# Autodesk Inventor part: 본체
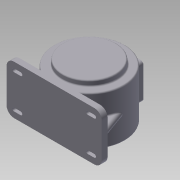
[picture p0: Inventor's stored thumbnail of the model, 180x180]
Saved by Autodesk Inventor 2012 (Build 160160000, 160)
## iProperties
Created: 2015-06
Part Number: 본체
Material: 알루미늄-6061
Document SubType Name: Modeling
Designer: User
Density: 2.71 g/cm^3
Mass: 3269.49 g
Surface Area: 2331.15 cm^2
Volume: 1206.45 cm^3
Author: User
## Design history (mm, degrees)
sketch "스케치1"
  geometry: C1 r 85 at (0, 0); 1 further point
  constraints: 1 centre point, 1 coincident
  dimensions: "d0" = 170 diameter of C1
extrude "돌출1" new body sketch "스케치1" distance "d1" = 118; taper "d2" = 0 deg
sketch "스케치2"
  geometry: L1 (-115, -85)-(115, -85); L2 (115, -85)-(115, -71); L3 (115, -71)-(-115, -71); L4 (-115, -71)-(-115, -85); C1 r 85 at (0, 0) reference; 1 further point
  constraints: 8 end point, 2 parallel, 1 horizontal, 1 midpoint, 1 perpendicular, 1 vertical alignment
  dimensions: "d3" = 14 distance of L3.end L1.start; "d4" = 85 distance from line of L1 C1.centre; "d5" = 230 distance of L1.start L1.end
extrude "돌출2" join sketch "스케치2" distance "d6" = 118; taper "d7" = 0 deg
sketch "스케치4"
  geometry: C1 r 65 at (0, 0); A1 r 85 centre (0, 0) between (46.733, -71) and (-46.733, -71) reference
  constraints: 1 centre point, 1 coincident
  dimensions: "d8" = 130 diameter of C1
extrude "돌출3" join sketch "스케치4" distance "d9" = 13; taper "d10" = 0 deg
sketch "스케치5"
  geometry: C1 r 65 at (0, 0); A1 r 85 centre (0, 0) between (46.733, -71) and (-46.733, -71) reference
  constraints: 1 centre point, 1 coincident
  dimensions: "d11" = 130 diameter of C1
extrude "돌출4" join sketch "스케치5" distance "d12" = 3; taper "d13" = 0 deg
sketch "스케치6"
  geometry: C1 r 65 at (0, 0) reference; C2 r 47.5 at (0, 0)
  constraints: 1 centre point, 1 coincident
  dimensions: "d14" = 95 diameter of C2
extrude "돌출5" cut sketch "스케치6" distance "d15" = 11; taper "d16" = 0 deg
sketch "스케치7"
  geometry: C1 r 47.5 at (0, 0) reference; C2 r 77 at (0, 0)
  constraints: 1 centre point, 1 coincident
  dimensions: "d17" = 154 diameter of C2
extrude "돌출6" cut sketch "스케치7" distance "d18" = 102; taper "d19" = 0 deg
sketch "스케치9"
  geometry: L1 (-77, 110)-(77, 110) reference; L2 (-71, 118)-(85, 118) reference; L3 (31, 110)-(29.368, 106.5); L4 (31, 110)-(34.862, 110); L5 (29.368, 106.5)-(0, 106.5); L6 (0, 110)-(0, 0); L7 (0, 110)-(0, 106.5)
  constraints: 11 end point, 2 point on line, 1 collinear, 1 equal length, 1 horizontal, 1 midpoint, 1 parallel, 1 perpendicular
  dimensions: "d23" = 115 deg angle of L3 L1; "d25" = 31 distance of L6.start L3.start; "d26" = 3.5 distance between parallel lines of L5 L1
revolve "회전1" sketch "스케치9" stored, may be unused: angle "d27" = 90 deg
sketch "스케치10"
  geometry: C1 r 29.368 at (0, 0) reference; C2 r 23.5 at (0, 0)
  constraints: 1 centre point, 1 coincident
  dimensions: "d28" = 47 diameter of C2
extrude "돌출7" cut sketch "스케치10" distance "d29" = 14; taper "d30" = 0 deg
sketch "스케치11"
  geometry: C1 r 23.5 at (0, 0) reference; C2 r 15 at (0, 0)
  constraints: 1 centre point, 1 coincident
  dimensions: "d31" = 30 diameter of C2
extrude "돌출8" cut sketch "스케치11" distance "d32" = 3; taper "d33" = 0 deg
node "작업 평면1"
sketch "스케치12"
  geometry: L1 (46.733, -71)-(115, -71) reference; L2 (-115, -71)-(-46.733, -71) reference; L3 (-115, -85)-(-115, -71) reference; L4 (-109, -71)-(-84.87, -4.703); A1 r 85 centre (0, 0) between (46.733, -71) and (-46.733, -71) reference; 1 further point
  constraints: 2 end point, 1 point on circle, 1 point on line
  dimensions: "d35" = 6 distance from line of L3 L4.start; "d36" = 110 deg angle of L4 L2
extrude "돌출9" join sketch "스케치12" stored distance "d37" = 15; taper "d38" = 0 deg
fillet "모깎기1" dims "d39" = 7.5
fillet "모깎기2" dims "d40" = 3
fillet "모깎기3" dims "d41" = 3
sketch "스케치13"
  geometry: L1 (68.267, 0)-(0, 0) reference; L2 (34, 9)-(18, 9); L3 (34, 27)-(18, 27); L4 (115, 0)-(115, 118); L5 (196, 27)-(212, 27); L6 (196, 9)-(212, 9); A1 r 9 centre (18, 18) between (18, 9) and (18, 27); A2 r 9 centre (34, 18) between (34, 27) and (34, 9); A3 r 9 centre (196, 18) between (204, 13.877) and (204, 22.123); A4 r 9 centre (212, 18) between (212, 9) and (212, 27); A5 r 9 centre (212, 18) between (204, 13.877) and (212, 9); A6 r 9 centre (196, 18) between (196, 9) and (204, 13.877); A7 r 9 centre (212, 18) between (204, 22.123) and (204, 13.877); A8 r 9 centre (196, 18) between (204, 22.123) and (196, 27); A9 r 9 centre (196, 18) between (196, 27) and (196, 9); A10 r 9 centre (212, 18) between (212, 27) and (204, 22.123); A11 r 9 centre (34, 18) between (34, 9) and (34, 27); A12 r 9 centre (18, 18) between (18, 27) and (18, 9)
  constraints: 26 point on circle, 12 centre point, 10 end point, 6 symmetric about line, 4 tangent, 1 horizontal, 1 perpendicular, 2 other
  dimensions: "d43" = 18 diameter of A1; "d44" = 18 diameter of A2; "d45" = 16 distance of L2.start L2.end; "d46" = 18 distance from line of L1 A1.centre; "d48" = 194 distance of A1.centre A4.centre
extrude "돌출10" join sketch "스케치13" distance "d49" = 3; taper "d50" = 0 deg
sketch "스케치14"
  geometry: L1 (196, 27)-(212, 27) reference; L2 (212, 9)-(196, 9) reference; L3 (212, 14)-(196, 14); L4 (196, 22)-(212, 22); A1 r 9 centre (212, 18) between (212, 9) and (212, 27) reference; A2 r 9 centre (196, 18) between (196, 27) and (196, 9) reference; A3 r 4 centre (212, 18) between (212, 14) and (212, 22); A4 r 4 centre (196, 18) between (196, 22) and (196, 14); 1 further point
  constraints: 4 end point, 4 point on circle, 2 centre point, 3 other
  dimensions: "d51" = 8 distance between parallel lines of L3 L4
extrude "돌출11" cut sketch "스케치14" stored distance "d52" = 3; taper "d53" = 0 deg
node "작업 평면2"
sketch "스케치15"
  geometry: L1 (-157.5, -16.5)-(-72.5, -16.5); L2 (-72.5, -16.5)-(-72.5, -101.5); L3 (-72.5, -101.5)-(-157.5, -101.5); L4 (-157.5, -101.5)-(-157.5, -16.5); L5 (-230, 0)-(-230, -118) reference; 4 further points
  constraints: 8 end point, 3 midpoint, 2 parallel, 1 horizontal, 1 horizontal alignment, 1 perpendicular, 1 vertical alignment
  dimensions: "d55" = 85 distance of L1.start L1.end; "d56" = 85 distance of L3.end L1.start
extrude "돌출12" join sketch "스케치15" stored distance "d57" = 3; taper "d58" = 0 deg
sketch "스케치16"
  geometry: L1 (-230, 0)-(-230, -118) reference; C1 r 35 at (-115, -59); 2 further points
  constraints: 1 centre point, 1 horizontal alignment, 1 midpoint, 1 vertical alignment
  dimensions: "d59" = 70 diameter of C1
extrude "돌출13" cut sketch "스케치16" stored distance "d60" = 3; taper "d61" = 0 deg
sketch "스케치17"
  geometry: L1 (-230, 0)-(-230, -118) reference; L2 (-150.5, -23.5)-(-79.5, -23.5); L3 (-79.5, -23.5)-(-79.5, -94.5); L4 (-79.5, -94.5)-(-150.5, -94.5); L5 (-150.5, -94.5)-(-150.5, -23.5); 8 further points
  constraints: 8 end point, 4 coincident, 3 midpoint, 2 parallel, 1 horizontal, 1 horizontal alignment, 1 perpendicular, 1 vertical alignment
  dimensions: "d63" = 71 distance of L3.end L4.end; "d64" = 71 distance of L4.end L2.start
hole "구멍1" sketch "스케치17" at (-150.5, -94.5), (-150.5, -23.5), (-79.5, -94.5), (-79.5, -23.5) diameter "d65" = 3.242; stored, may be unused: countersink angle "d69" = 90 deg, drill point angle "d71" = 118 deg; dims "d66" = 10, "d67" = 4, "d68" = 2, "d70" = 13
fillet "모깎기4" dims "d72" = 7
fillet "모깎기5" dims "d73" = 18
fillet "모깎기6" dims "d74" = 0.3
sketch "스케치18" dims "d75" = 110
  geometry: C1 r 47.5 at (0, 0) reference; C2 r 65 at (0, 0) reference; 2 further points
  constraints: 2 vertical alignment, 1 coincident, 2 other
hole "구멍2" sketch "스케치18" at (0, 55) diameter "d76" = 3.242; stored, may be unused: countersink angle "d80" = 90 deg, drill point angle "d82" = 118 deg; dims "d77" = 15, "d78" = 4, "d79" = 2, "d81" = 34.5
node "작업축1"
node "작업 평면5"
  node "작업 평면4"
sketch "스케치20"
  geometry: L1 (-6.549, 10.12)-(-6.549, 107.88); L2 (-6.549, 107.88)-(6.549, 107.88); L3 (6.549, 107.88)-(6.549, 10.12); L4 (6.549, 10.12)-(-6.549, 10.12); L5 (125.637, 100)-(125.637, 18) reference; 4 further points
  constraints: 3 midpoint, 1 horizontal alignment, 1 vertical alignment, 2 other
feature "엠보싱1" sketch "스케치20" dims "d9" = 13, "d10" = 0, "d89" = 0.5, "d90" = 0
fillet "모깎기7" dims "d91" = 3
fillet "모깎기8" dims "d92" = 3
chamfer "모따기1" distance "d93" = 1; stored, may be unused: second distance "d94" = 2, angle "d95" = 45 deg
fillet "모깎기9" dims "d96" = 3
fillet "모깎기10" dims "d97" = 3
fillet "모깎기11" dims "d98" = 3
fillet "모깎기12" dims "d99" = 3
node "솔리드1"
mirror "대칭1"
mirror "대칭2"
mirror "대칭3"
pattern_circular "원형 패턴1" dims angle "d84" = 360 deg
node "작업 평면3"
other parameters: "d34" = -59, "d54" = -173, "d86" = -25 deg, "d87" = 90 deg, "d88" = -137
